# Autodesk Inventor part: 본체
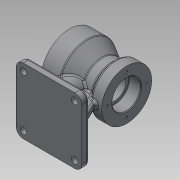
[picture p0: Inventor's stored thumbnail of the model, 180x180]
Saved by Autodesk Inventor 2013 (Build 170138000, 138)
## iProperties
Created: 2019-01
Part Number: 본체
Material: 일반
Document SubType Name: Modeling
Designer: hana-cad16
Density: 1 g/cm^3
Author: hana-cad16
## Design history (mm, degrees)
sketch "스케치1"
  geometry: L1 (0, 0)-(80, 0); L2 (0, 26)-(0, 40); L3 (0, 40)-(25, 40); L4 (80, 20)-(80, 35); L5 (80, 35)-(65, 35); L6 (25, 40)-(43.113, 29.543); L7 (45.785, 28)-(59.126, 28); L8 (43.113, 29.543)-(45.785, 28); L9 (65, 35)-(59.126, 28); L10 (0, 26)-(20, 26); L11 (20, 26)-(20, 16); L12 (80, 20)-(63, 20); L13 (20, 16)-(63, 16); L14 (63, 16)-(63, 20)
  constraints: 28 end point, 5 perpendicular, 1 collinear, 1 horizontal, 1 parallel
  dimensions: "d2" = 25 distance of L2.end L3.end; "d3" = 70 diameter of L4.end L1; "d10" = 32 diameter of L11.end L1
revolve "회전1" sketch "스케치1" stored, may be unused: angle "d13" = 90 deg
chamfer "모따기1" distance "d14" = 1; stored, may be unused: second distance "d15" = 2, angle "d16" = 45 deg
fillet "모깎기1" dims "d17" = 1
fillet "모깎기2" dims "d18" = 0.6
sketch "스케치3" dims "d19" = 55
  geometry: C1 r 21 at (0, 0) reference; C2 r 3.873 at (0, 27.5); 1 further point
  constraints: 1 centre point, 1 coincident, 1 vertical alignment, 2 other
hole "구멍1" sketch "스케치3" at (0, 27.5) diameter "d20" = 3.242; stored, may be unused: countersink angle "d24" = 90 deg, drill point angle "d26" = 118 deg; dims "d21" = 9, "d22" = 4, "d23" = 2, "d25" = 11
sketch "스케치4" dims "d30" = 66
  geometry: C1 r 27 at (0, 0) reference; C2 r 3.501 at (0, 33); 1 further point
  constraints: 1 centre point, 1 coincident, 1 vertical alignment, 2 other
hole "구멍2" sketch "스케치4" at (0, 33) diameter "d31" = 3.242; stored, may be unused: countersink angle "d35" = 90 deg, drill point angle "d37" = 118 deg; dims "d32" = 9, "d33" = 4, "d34" = 2, "d36" = 11
node "작업 평면1"
sketch "스케치5"
  geometry: L1 (0, 40)-(0, -40) reference; L2 (0, 0)-(-5, 0); L3 (-5, 0)-(-5, -46); L4 (-5, 0)-(-5, 46); L5 (-5, -46)-(-97, -46); L6 (-97, -46)-(-97, 46); L7 (-97, 46)-(-5, 46); L8 (-5, 46)-(-5, -46)
  constraints: 14 end point, 3 equal length, 3 perpendicular, 1 horizontal
  dimensions: "d45" = 92 distance of L6.end L7.end
extrude "돌출1" join sketch "스케치5" distance "d46" = 10; taper "d47" = 0 deg
fillet "모깎기3" dims "d48" = 10
sketch "스케치6"
  geometry: C1 r 4.5 at (15, 36); C2 r 4.5 at (87, 36); C3 r 4.5 at (15, -36); C4 r 4.5 at (87, -36); A1 r 10 centre (15, -36) between (5, -36) and (15, -46) reference; A2 r 10 centre (87, -36) between (87, -46) and (97, -36) reference; A3 r 10 centre (87, 36) between (97, 36) and (87, 46) reference; A4 r 10 centre (15, 36) between (15, 46) and (5, 36) reference; 1 further point
  constraints: 4 centre point, 4 coincident
  dimensions: "d49" = 9 diameter of C1; "d50" = 9 diameter of C2; "d51" = 9 diameter of C3; "d52" = 9 diameter of C4
extrude "돌출2" cut sketch "스케치6" stored distance "d53" = 10; taper "d54" = 0 deg
sketch "스케치7"
  geometry: L1 (97, -36)-(97, 36) reference; L2 (5, 36)-(5, -36) reference; L3 (87, 46)-(15, 46) reference; L4 (5, 0)-(5, 46); L5 (5, 46)-(35, 46); L6 (5, 0)-(97, 0); C1 r 16 at (35, 0); 1 further point
  constraints: 6 end point, 2 midpoint, 2 point on line, 1 centre point
  dimensions: "d55" = 46 distance of L4.start L4.end; "d56" = 30 distance of L4.end L5.end; "d57" = 32 diameter of C1
fillet "모깎기4" dims "d58" = 3
extrude "돌출3" join sketch "스케치7" stored distance "d59" = 10; taper "d60" = 0 deg
sketch "스케치8"
  geometry: L1 (97, -70)-(97, -80) reference; L2 (97, -70)-(87, -70); L3 (87, -70)-(68.58, -30.499); L4 (68.58, -30.499)-(56.144, -25.185); L5 (56.144, -25.185)-(45.332, -25.185); L6 (45.332, -25.185)-(45.332, -73.432); L7 (45.332, -73.432)-(78.814, -75); L8 (78.814, -75)-(92, -70); 1 further point
  constraints: 14 end point, 2 perpendicular, 1 midpoint, 1 parallel
  dimensions: "d61" = 10 distance of L1.start L2.end; "d62" = 25 deg angle of L1 L3
extrude "돌출4" join sketch "스케치8" stored distance "d63" = 10; taper "d64" = 0 deg
fillet "모깎기5" dims "d65" = 3
fillet "모깎기6" dims "d66" = 3
fillet "모깎기7" dims "d67" = 3
node "솔리드1"
pattern_circular "원형 패턴1" dims angle "d28" = 360 deg
pattern_circular "원형 패턴2" dims angle "d39" = 360 deg
